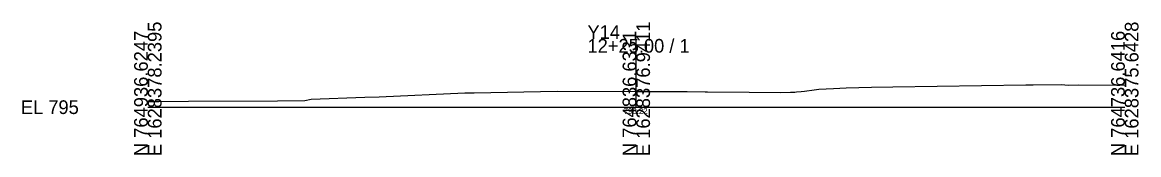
# Model space of a CAD drawing. Extents: x -26 to 1403, y -10 to 4517.
# Drawn here: x -25.7 to 202.8, y 4490.3 to 4517.3 of the extents above; entities that cross this region are included whole.
import ezdxf

# ---------------------------------------------------------------- set-up
doc = ezdxf.new("R2010")
doc.units = 0
for name, color, linetype in [('Default', 7, 'Continuous'), ('Exist Cross Section Cell', 7, 'Continuous'), ('Exist XS Center Line Elevation Label', 7, 'Continuous'), ('Exist XS Ground Line', 7, 'Continuous')]:
    doc.layers.add(name, color=color, linetype=linetype)

msp = doc.modelspace()

# ---------------------------------------------------------------- linework, layer by layer
at = {"layer": 'Exist Cross Section Cell'}
for p, q in [((100, 4500), (100, 4513.94)), ((0, 4500), (100, 4500)), ((100, 4500), (200, 4500))]:
    msp.add_line(p, q, dxfattribs=at)
at = {"layer": 'Exist XS Ground Line'}
msp.add_lwpolyline([(0, 4501.14), (1.02, 4501.14), (2.27, 4501.15), (8.3, 4501.21), (26.52, 4501.33), (32.16, 4501.34), (33.47, 4501.61), (44.45, 4502.07), (47.36, 4502.11), (64.88, 4502.9), (66.79, 4502.96), (83.79, 4503.24), (100, 4503.22), (110.38, 4503.21), (114.07, 4503.12), (114.58, 4503.12), (123.07, 4503.05), (129.56, 4503.03), (131.57, 4503.08), (132.46, 4503.08), (132.79, 4503.12), (133.73, 4503.19), (134.44, 4503.25), (134.93, 4503.33), (135.94, 4503.46), (137.39, 4503.65), (140.39, 4503.83), (142.96, 4503.98), (148.12, 4504.08), (152.52, 4504.14), (179.72, 4504.55), (181.27, 4504.55), (187.09, 4504.65), (187.73, 4504.57), (188.42, 4504.53), (190.44, 4504.54), (200, 4504.48)], dxfattribs=at)

# ---------------------------------------------------------------- texts
at = {"layer": 'Default'}
msp.add_text('-', height=0.0001, dxfattribs=at).set_placement((0, 4500))
at = {"layer": 'Exist Cross Section Cell'}
for s, p in [('E 1628378.2395', (2.8, 4490)), ('E 1628376.9411', (102.8, 4490)), ('E 1628375.6428', (202.8, 4490)), ('N 764936.6247', (0, 4490)), ('N 764836.6331', (100, 4490)), ('N 764736.6416', (200, 4490))]:
    msp.add_text(s, height=2.8, rotation=90, dxfattribs=at).set_placement(p)
for s, p in [('Y14', (90, 4513.94)), ('12+25.00 / 1', (90, 4511.14)), ('EL 795', (-26, 4498.6))]:
    msp.add_text(s, height=2.8, dxfattribs=at).set_placement(p)
at = {"layer": 'Exist XS Center Line Elevation Label'}
msp.add_text('798.22', height=1.2, dxfattribs=at).set_placement((97.41, 4498.62))

doc.saveas('drawing.dxf')
